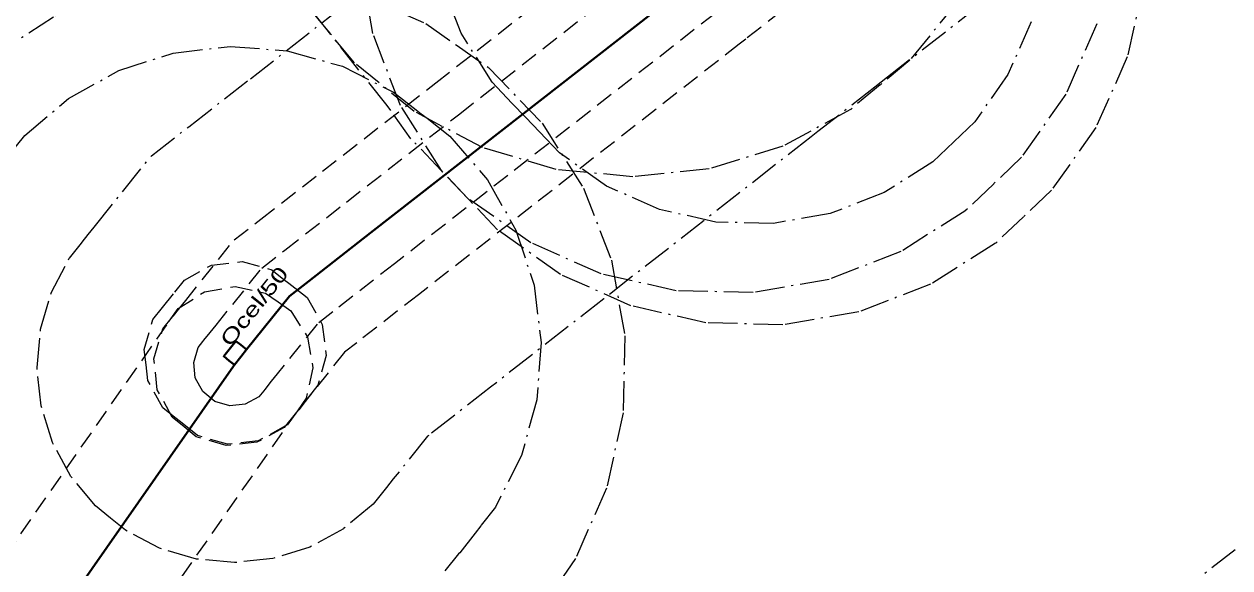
# Model space of a CAD drawing. Extents: x -588392 to -586332, y -1208963 to -1206334.
# Drawn here: x -587924.1 to -587862.4, y -1206855.9 to -1206828.1 of the extents above; entities that cross this region are included whole.
import ezdxf

# ---------------------------------------------------------------- set-up
doc = ezdxf.new("R2010")
doc.units = 0
doc.header["$LTSCALE"] = 0.3
doc.linetypes.add('DOT_DASHED', pattern=[7.7, 5, -1.2, 0.3, -1.2])
doc.linetypes.add('MEDIUM_DASHED', pattern=[4.5, 3, -1.5])
for name, color, linetype, lineweight in [('1', 7, 'MEDIUM_DASHED', 13), ('34', 7, 'Continuous', 40), ('35', 7, 'Continuous', 35), ('51', 7, 'MEDIUM_DASHED', 13)]:
    doc.layers.add(name, color=color, linetype=linetype, lineweight=lineweight)
doc.layers.add('40', color=7, linetype='Continuous')

msp = doc.modelspace()

# ---------------------------------------------------------------- linework, layer by layer
at = {"layer": '1'}
msp.add_lwpolyline([(-587884.212, -1206826.591), (-587887.131, -1206828.865), (-587887.47, -1206829.129), (-587898.08, -1206837.414), (-587903.886, -1206841.938), (-587907.043, -1206844.397), (-587907.663, -1206844.879), (-587909.556, -1206847.239), (-587909.856, -1206847.614), (-587910.194, -1206848.036), (-587910.251, -1206848.107), (-587910.752, -1206848.725), (-587912.15, -1206849.485), (-587913.733, -1206849.651), (-587915.259, -1206849.2), (-587915.877, -1206848.699), (-587916.495, -1206848.198), (-587917.255, -1206846.8), (-587917.421, -1206845.217), (-587916.97, -1206843.691), (-587916.469, -1206843.073), (-587916.424, -1206843.018), (-587916.1, -1206842.614), (-587915.8, -1206842.239), (-587913.317, -1206839.141), (-587911.957, -1206838.083), (-587908.802, -1206835.626), (-587903, -1206831.106), (-587892.392, -1206822.823)], dxfattribs=at)
at = {"layer": '1', "linetype": 'DOT_DASHED'}
for points in [[(-587866.731, -1206825.939), (-587867.602, -1206829.781), (-587869.206, -1206833.38), (-587871.481, -1206836.596), (-587872.911, -1206837.951), (-587874.341, -1206839.306), (-587877.674, -1206841.407), (-587881.352, -1206842.816), (-587885.236, -1206843.482), (-587889.174, -1206843.376), (-587893.016, -1206842.505), (-587896.615, -1206840.901), (-587899.831, -1206838.626), (-587901.186, -1206837.196), (-587901.35, -1206837.023), (-587902.705, -1206835.593), (-587904.806, -1206832.26), (-587906.215, -1206828.582), (-587906.881, -1206824.698)], [(-587980.539, -1206914.219), (-587943.819, -1206854.247), (-587929.75, -1206834.129), (-587928.621, -1206832.515), (-587925.777, -1206829.788), (-587922.456, -1206827.669), (-587918.785, -1206826.239), (-587914.906, -1206825.553), (-587910.967, -1206825.636), (-587907.12, -1206826.487), (-587903.513, -1206828.071), (-587901.899, -1206829.2), (-587900.285, -1206830.329), (-587897.558, -1206833.173), (-587895.439, -1206836.494), (-587894.009, -1206840.165), (-587893.323, -1206844.044), (-587893.406, -1206847.983), (-587894.257, -1206851.83), (-587895.841, -1206855.437), (-587896.97, -1206857.051), (-587910.341, -1206876.173), (-587946.581, -1206935.361)], [(-587872.52, -1206827.98), (-587873.715, -1206830.682), (-587875.415, -1206833.099), (-587876.484, -1206834.119), (-587877.553, -1206835.138), (-587880.048, -1206836.721), (-587882.804, -1206837.786), (-587885.715, -1206838.294), (-587888.669, -1206838.223), (-587891.552, -1206837.578), (-587894.254, -1206836.383), (-587896.671, -1206834.683), (-587897.691, -1206833.614), (-587898.391, -1206832.88), (-587899.1, -1206832.136), (-587900.119, -1206831.066), (-587901.701, -1206828.571), (-587902.765, -1206825.815)], [(-587869.154, -1206828.082), (-587870.749, -1206831.685), (-587873.015, -1206834.907), (-587874.441, -1206836.266), (-587875.867, -1206837.625), (-587879.194, -1206839.735), (-587882.869, -1206841.155), (-587886.75, -1206841.83), (-587890.689, -1206841.736), (-587894.533, -1206840.875), (-587898.136, -1206839.28), (-587901.358, -1206837.014), (-587902.717, -1206835.588), (-587904.269, -1206833.96), (-587905.304, -1206832.517), (-587905.492, -1206832.269), (-587908.696, -1206828.217), (-587909.918, -1206826.672)], [(-587876.248, -1206826.896), (-587878.733, -1206829.953), (-587880.25, -1206831.21), (-587881.767, -1206832.467), (-587885.232, -1206834.34), (-587888.997, -1206835.502), (-587892.916, -1206835.906), (-587896.838, -1206835.539), (-587900.613, -1206834.413), (-587904.096, -1206832.572), (-587907.153, -1206830.087), (-587908.41, -1206828.57), (-587908.7, -1206828.22), (-587909.343, -1206827.445)], [(-587924.947, -1206834.943), (-587924.032, -1206833.798), (-587921.792, -1206831.905), (-587919.228, -1206830.481), (-587916.436, -1206829.582), (-587913.524, -1206829.24), (-587910.6, -1206829.468), (-587907.776, -1206830.258), (-587905.158, -1206831.581), (-587904.002, -1206832.483), (-587903.744, -1206832.684), (-587903.444, -1206832.918), (-587902.28, -1206833.827), (-587900.351, -1206836.066), (-587898.896, -1206838.637), (-587897.97, -1206841.443), (-587897.61, -1206844.376), (-587897.828, -1206847.323), (-587898.618, -1206850.17), (-587899.948, -1206852.809), (-587900.668, -1206853.731), (-587900.684, -1206853.762), (-587900.984, -1206854.135), (-587901.766, -1206855.137), (-587901.838, -1206855.199), (-587902.534, -1206856.066)], [(-587862.086, -1206854.989), (-587864.998, -1206857.257)]]:
    msp.add_lwpolyline(points, dxfattribs=at)
at = {"layer": '1'}
for points in [[(-587910.016, -1206847.828), (-587910.036, -1206847.839), (-587910.189, -1206848.03), (-587910.687, -1206848.651), (-587912.082, -1206849.416), (-587913.664, -1206849.59), (-587915.191, -1206849.145), (-587915.812, -1206848.647), (-587916.072, -1206848.439), (-587916.351, -1206848.216), (-587916.973, -1206847.719), (-587917.742, -1206846.325), (-587917.83, -1206845.534), (-587917.918, -1206844.743), (-587917.477, -1206843.214), (-587916.98, -1206842.593), (-587916.355, -1206841.811), (-587915.862, -1206841.194), (-587914.481, -1206840.428), (-587912.912, -1206840.243), (-587911.391, -1206840.669), (-587910.769, -1206841.155), (-587910.513, -1206841.354), (-587910.216, -1206841.587), (-587909.589, -1206842.077), (-587908.805, -1206843.461), (-587908.611, -1206845.041), (-587909.036, -1206846.574), (-587909.526, -1206847.201)], [(-588067.296, -1207023.415), (-588071.718, -1207016.748), (-588015.036, -1206978.122), (-587990.063, -1206959.18), (-587966.956, -1206922.676), (-587930.428, -1206863.017), (-587916.638, -1206843.298), (-587916.182, -1206842.646), (-587914.841, -1206841.79), (-587913.274, -1206841.513), (-587911.72, -1206841.856), (-587911.068, -1206842.312), (-587910.416, -1206842.768), (-587909.56, -1206844.109), (-587909.283, -1206845.676), (-587909.626, -1206847.23), (-587910.082, -1206847.882), (-587923.732, -1206867.403), (-587960.164, -1206926.904), (-587984.077, -1206964.68), (-588010.364, -1206984.618)]]:
    msp.add_lwpolyline(points, close=True, dxfattribs=at)
at = {"layer": '34'}
for points in [[(-587822.287, -1206773.226), (-587866.8, -1206807.94), (-587877.576, -1206816.344), (-587886.023, -1206822.931), (-587886.671, -1206823.436), (-587889.59, -1206825.71), (-587889.931, -1206825.976), (-587900.54, -1206834.26), (-587906.344, -1206838.782), (-587909.5, -1206841.24), (-587910.49, -1206842.01), (-587912.678, -1206844.739), (-587912.978, -1206845.114), (-587913.309, -1206845.527), (-587913.36, -1206845.59)], [(-587913.309, -1206845.527), (-587913.572, -1206845.316), (-587913.855, -1206845.09), (-587913.23, -1206844.308), (-587912.975, -1206844.507), (-587912.678, -1206844.739)], [(-587913.36, -1206845.59), (-587927.08, -1206865.21), (-587963.56, -1206924.79), (-587987.07, -1206961.93), (-588012.7, -1206981.37), (-588069.507, -1207020.082)]]:
    msp.add_lwpolyline(points, dxfattribs=at)
at = {"layer": '35'}
msp.add_lwpolyline([(-587822.287, -1206773.226), (-587866.8, -1206807.94), (-587877.576, -1206816.344), (-587886.023, -1206822.931), (-587886.671, -1206823.436), (-587889.59, -1206825.71), (-587889.931, -1206825.976), (-587900.54, -1206834.26), (-587906.344, -1206838.782), (-587909.5, -1206841.24), (-587910.49, -1206842.01), (-587912.678, -1206844.739), (-587912.978, -1206845.114), (-587913.309, -1206845.527), (-587913.36, -1206845.59)], dxfattribs=at)
at = {"layer": '51', "linetype": 'DOT_DASHED'}
msp.add_lwpolyline([(-587871.426, -1206824.23), (-587879.875, -1206830.818), (-587880.525, -1206831.324), (-587883.442, -1206833.597), (-587883.778, -1206833.859), (-587894.39, -1206842.145), (-587900.199, -1206846.671), (-587903.358, -1206849.132), (-587903.423, -1206849.182), (-587904.873, -1206850.99), (-587905.172, -1206851.364), (-587905.521, -1206851.8), (-587905.588, -1206851.882), (-587906.208, -1206852.647), (-587907.722, -1206853.907), (-587909.453, -1206854.847), (-587911.334, -1206855.432), (-587913.293, -1206855.638), (-587915.254, -1206855.458), (-587917.143, -1206854.899), (-587918.887, -1206853.982), (-587919.652, -1206853.362), (-587920.417, -1206852.742), (-587921.677, -1206851.228), (-587922.617, -1206849.497), (-587923.202, -1206847.616), (-587923.408, -1206845.657), (-587923.228, -1206843.696), (-587922.669, -1206841.807), (-587921.752, -1206840.063), (-587921.132, -1206839.298), (-587921.097, -1206839.254), (-587920.784, -1206838.864), (-587920.483, -1206838.488), (-587917.557, -1206834.838), (-587915.642, -1206833.348), (-587912.489, -1206830.893), (-587906.69, -1206826.375)], dxfattribs=at)
at = {"layer": '51'}
msp.add_lwpolyline([(-587888.7, -1206827.553), (-587899.31, -1206835.837), (-587905.115, -1206840.36), (-587908.272, -1206842.818), (-587909.077, -1206843.444), (-587911.117, -1206845.989), (-587911.417, -1206846.364), (-587911.751, -1206846.782), (-587911.806, -1206846.848), (-587912.056, -1206847.157), (-587912.755, -1206847.537), (-587913.546, -1206847.62), (-587914.309, -1206847.394), (-587914.618, -1206847.144), (-587914.927, -1206846.894), (-587915.307, -1206846.195), (-587915.39, -1206845.404), (-587915.164, -1206844.641), (-587914.914, -1206844.332), (-587914.867, -1206844.272), (-587914.539, -1206843.864), (-587914.239, -1206843.489), (-587911.903, -1206840.576), (-587910.728, -1206839.662), (-587907.573, -1206837.204), (-587901.77, -1206832.683), (-587891.162, -1206824.399)], dxfattribs=at)

# ---------------------------------------------------------------- texts
at = {"layer": '40', "width": 1.4}
msp.add_text('Ocel/50', height=0.75, rotation=51.367, dxfattribs=at).set_placement((-587913.511, -1206844.659))

doc.saveas('drawing.dxf')
